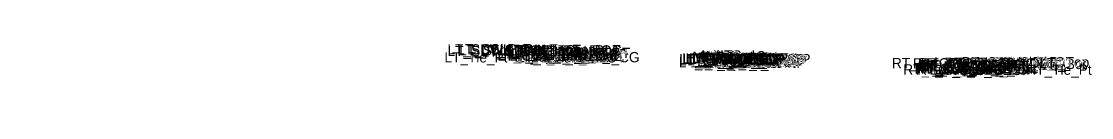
# Model space of a CAD drawing. Extents: x -26 to 4229, y -10 to 9523.
# Drawn here: x 4000 to 4209.1, y 2000 to 2010 of the extents above; entities that cross this region are included whole.
import ezdxf

# ---------------------------------------------------------------- set-up
doc = ezdxf.new("R2010")
doc.units = 0
doc.layers.add('Default', color=7, linetype='Continuous')

msp = doc.modelspace()

# ---------------------------------------------------------------- texts
at = {"layer": 'Default'}
for s, height, p in [('LT_SDWK_Out_Top', 2, (4083.24, 2007.94)), ('LT_CSLP_Pnt', 2, (4085.17, 2007.97)), ('LT_Sub_Trench_Out_DLT', 2, (4085.57, 2007.77)), ('LT_SDWK_In_Top', 2, (4089.86, 2007.84)), ('LT_CG_Top_Face', 2, (4094.76, 2007.73)), ('LT_CG_Top_BOC', 2, (4095.28, 2007.73)), ('LT_Tie_Pt', 2, (4082.66, 2006.38)), ('LT_SDWK_Out_Bot', 2, (4083.27, 2007.61)), ('LT_SDWK_In_Bot', 2, (4089.89, 2007.51)), ('LT_CG1_Shelf_Out', 2, (4093.05, 2006.76)), ('LT_CG_Bot_BOC', 2, (4095.31, 2006.74)), ('LT_CG_Top_Gut', 2, (4095.74, 2007.23)), ('LT_Sub_OEOP', 2, (4096.37, 2006.52)), ('LT_Sub_OEOT_CG', 2, (4096.87, 2006.41)), ('LT_CG_Bot_IE', 2, (4099.41, 2006.66)), ('LT_Sub_OEOT', 2, (4099.58, 2006.37)), ('LT_PV2_OEOT', 2, (4099.67, 2007)), ('LT_PV3_OEOT', 2, (4099.67, 2006.75)), ('LT_PV1_OEOT', 2, (4100.24, 2007.25)), ('LT_PV2_OEEOP', 2, (4128.56, 2006.05)), ('LT_PV3_OEEOP', 2, (4128.56, 2005.8)), ('LT_PV1_OEEOP', 2, (4129.12, 2006.18)), ('LT_PV2_IEEOP', 2, (4129.2, 2006.05)), ('LT_PV1_IEEOP', 2, (4129.77, 2006.18)), ('LT_PV2_PGL1', 2, (4130.13, 2006.05)), ('LT_PV3_PGL1', 2, (4130.13, 2005.8)), ('LT_PV2_PGL', 2, (4130.46, 2006.05)), ('LT_PV1_PGL', 2, (4131.03, 2006.3)), ('MI_Face In', 2, (4131.15, 2006.47)), ('MI_Bot In', 2, (4132.13, 2006.3)), ('RT_PV2_OEEOP', 2, (4132.51, 2005.92)), ('RT_PV3_OEEOP', 2, (4132.51, 2005.67)), ('MI_Top In', 2, (4132.86, 2006.72)), ('RT_PV1_OEEOP', 2, (4133.08, 2006.05)), ('RT_PV2_IEEOP', 2, (4133.16, 2005.92)), ('MI_Face Out', 2, (4133.51, 2006.34)), ('MI_Top Out', 2, (4133.72, 2006.59)), ('RT_PV1_IEEOP', 2, (4133.72, 2006.05)), ('RT_PV2_PGL1', 2, (4134.08, 2005.92)), ('RT_PV3_PGL1', 2, (4134.08, 2005.67)), ('MI_Crown', 2, (4134.32, 2006.74)), ('RT_PV2_PGL', 2, (4134.42, 2005.92)), ('MI_Bot Out', 2, (4134.51, 2006.17)), ('RT_PV1_PGL', 2, (4134.98, 2006.17)), ('LT_Sub_OEEOP', 2, (4128.46, 2005.43)), ('LT_PV4_PGL', 2, (4130.46, 2005.43)), ('RT_Sub_OEEOP', 2, (4132.42, 2005.3)), ('RT_PV4_PGL', 2, (4134.42, 2005.3)), ('RT_Sub_Trench_Out_DLT', 2, (4170.11, 2005.25)), ('RT_Sub_OEOT_CG', 2, (4172.32, 2004.02)), ('RT_CG_Top_Face', 2, (4174.21, 2005.21)), ('RT_CG1_Shelf_Out', 2, (4174.5, 2004.17)), ('RT_CG_Bot_IE', 2, (4174.87, 2004.27)), ('RT_Sub_OEOT', 2, (4175.03, 2003.97)), ('RT_PV2_OEOT', 2, (4175.13, 2004.6)), ('RT_PV3_OEOT', 2, (4175.13, 2004.35)), ('RT_CG_Top_Gut', 2, (4175.19, 2004.71)), ('RT_PV1_OEOT', 2, (4175.69, 2004.85)), ('RT_CG_Top_BOC', 2, (4175.74, 2005.21)), ('RT_CG_Bot_BOC', 2, (4175.77, 2004.19)), ('RT_Sub_OEOP', 2, (4178.32, 2003.91)), ('RT_SDWK_In_Top', 2, (4180.31, 2005.32)), ('RT_SDWK_In_Bot', 2, (4180.34, 2004.98)), ('RT_SDWK_Out_Top', 2, (4183.69, 2005.42)), ('RT_SDWK_Out_Bot', 2, (4183.72, 2005.08)), ('RT_Shld_O', 2, (4190.04, 2005.41)), ('CSLP_Pnt', 2, (4192.37, 2005.45)), ('RT_Tie_Pt', 2, (4196.36, 2003.96)), ('-', 0.0001, (4000, 2000)), ('-', 0.0001, (4000, 2000)), ('-', 0.0001, (4000, 2000)), ('-', 0.0001, (4000, 2000)), ('-', 0.0001, (4000, 2000)), ('-', 0.0001, (4000, 2000)), ('-', 0.0001, (4000, 2000))]:
    msp.add_text(s, height=height, dxfattribs=at).set_placement(p)

doc.saveas('drawing.dxf')
